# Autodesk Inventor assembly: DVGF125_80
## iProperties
Created: 2010-04
Part Number: DVGF125_80
Document SubType Name: Assembly
Designer: TB
Mass: 4992.94 g
Surface Area: 4444.19 cm^2
Volume: 4992.94 cm^3
Density: 1 g/cm^3
Description: KM DVGF 125/80 - 100 mm
Slaglengde: 100.000 mm
Author: TB
